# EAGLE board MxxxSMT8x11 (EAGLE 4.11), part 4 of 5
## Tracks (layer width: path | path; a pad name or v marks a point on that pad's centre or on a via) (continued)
M5  (via drill 0.61) (continued)
  Bottom 0.254: v88.9,160.02 v83.82,160.02 83.57,160.27 72.64,160.27 v72.39,160.53 | v100.33,162.81 99.31,163.83 92.71,163.83 v90.17,161.29 | v22.86,167.39 13.97,167.39 U$9.M2 | v22.86,164.08 v35.56,164.08 35.81,164.08 55.63,164.08 v55.88,163.83
M6  (via drill 0.61)
  Top 0.254: E62.13 99.31,159 101.35,159 101.35,164.34 92.96,172.72 91.44,172.72 v91.44,169.16 91.44,164.85 92.46,163.83 E59.6 | v29.46,166.12 29.46,164.08 30.23,164.08 E56.6 32,163.83 32.51,163.32 32.51,162.05 v35.56,159 | v14.73,166.37 13.97,167.13 U$9.M1 | v45.72,167.13 v45.72,175.01 44.7,175.01 E44.2 | v49.53,159 50.55,159 E47.13 | v62.23,175.26 63.25,175.26 E51.13 | E54.12 74.68,176.28 v73.66,176.28 73.91,176.02 73.91,171.7 v75.18,170.43
  Bottom 0.254: v14.73,166.37 29.21,166.37 v29.46,166.12 29.72,166.37 44.96,166.37 v45.72,167.13 | v35.56,159 v49.53,159 | v45.72,175.01 61.98,175.01 v62.23,175.26 62.48,175.51 63.25,176.28 v73.66,176.28 | v91.44,169.16 91.19,169.42 76.2,169.42 v75.18,170.43
M7  (via drill 0.61)
  Top 0.254: v172.72,166.37 173.74,166.37 E74.3 | E80.12 168.66,166.37 v167.64,166.37 167.39,166.12 v166.37,165.1 | v184.15,165.86 184.15,165.35 185.17,165.35 E71.4 186.94,165.1 188.98,163.07 188.98,160.53 194.56,160.53 195.33,161.29 195.33,162.31 197.87,162.31 E68.6 199.64,162.56 v200.66,162.56 | v156.21,163.58 157.23,163.58 E83.10 | v233.68,159 v233.68,162.31 232.66,162.31 E77.9 | v220.98,162.31 219.96,162.31 E66.9
  Bottom 0.254: v167.64,166.37 v172.72,166.37 172.97,166.12 183.9,166.12 v184.15,165.86 | v156.21,163.58 157.23,162.56 163.83,162.56 v166.37,165.1 | v233.68,159 242.57,159 U$12.M2 | v233.68,162.31 v220.98,162.31 220.73,162.31 200.91,162.31 v200.66,162.56
M8  (via drill 0.61)
  Top 0.254: E83.13 157.23,167.39 155.19,167.39 155.19,162.05 163.58,153.67 165.1,153.67 v165.1,157.23 165.1,161.54 164.08,162.56 E80.6 | v227.08,160.27 227.08,162.31 226.31,162.31 E77.6 224.54,162.56 224.03,163.07 224.03,164.34 v220.98,167.39 | v241.81,160.02 242.57,159.26 U$12.M1 | v210.82,159.26 v210.82,151.38 211.84,151.38 E65.2 | v207.01,167.39 205.99,167.39 E68.13 | v194.31,151.13 193.29,151.13 E72.13 | E75.12 181.86,150.11 v182.88,150.11 182.63,150.37 182.63,154.69 v181.36,155.96
  Bottom 0.254: v241.81,160.02 227.33,160.02 v227.08,160.27 226.82,160.02 211.58,160.02 v210.82,159.26 | v220.98,167.39 v207.01,167.39 | v210.82,151.38 194.56,151.38 v194.31,151.13 194.06,150.88 193.29,150.11 v182.88,150.11 | v165.1,157.23 165.35,156.97 180.34,156.97 v181.36,155.96
M9  (via drill 0.61)
  Top 0.254: v172.72,100.33 173.74,100.33 E95.3 | E101.12 168.66,100.33 v167.64,100.33 167.39,100.08 v166.37,99.06 | v184.15,99.82 184.15,99.31 185.17,99.31 E92.4 186.94,99.06 188.98,97.03 188.98,94.49 194.56,94.49 195.33,95.25 195.33,96.27 197.87,96.27 E89.6 199.64,96.52 v200.66,96.52 | v156.21,97.54 157.23,97.54 E104.10 | v233.68,92.96 v233.68,96.27 232.66,96.27 E98.9 | v220.98,96.27 219.96,96.27 E87.9
  Bottom 0.254: v167.64,100.33 v172.72,100.33 172.97,100.08 183.9,100.08 v184.15,99.82 | v156.21,97.54 157.23,96.52 163.83,96.52 v166.37,99.06 | v233.68,92.96 242.57,92.96 U$15.M2 | v233.68,96.27 v220.98,96.27 220.73,96.27 200.91,96.27 v200.66,96.52
M10  (via drill 0.61)
  Top 0.254: E104.13 157.23,101.35 155.19,101.35 155.19,96.01 163.58,87.63 165.1,87.63 v165.1,91.19 165.1,95.5 164.08,96.52 E101.6 | v227.08,94.23 227.08,96.27 226.31,96.27 E98.6 224.54,96.52 224.03,97.03 224.03,98.3 v220.98,101.35 | v241.81,93.98 242.57,93.22 U$15.M1 | v210.82,93.22 v210.82,85.34 211.84,85.34 E86.2 | v207.01,101.35 205.99,101.35 E89.13 | v194.31,85.09 193.29,85.09 E93.13 | E96.12 181.86,84.07 v182.88,84.07 182.63,84.33 182.63,88.65 v181.36,89.92
  Bottom 0.254: v241.81,93.98 227.33,93.98 v227.08,94.23 226.82,93.98 211.58,93.98 v210.82,93.22 | v220.98,101.35 v207.01,101.35 | v210.82,85.34 194.56,85.34 v194.31,85.09 194.06,84.84 193.29,84.07 v182.88,84.07 | v165.1,91.19 165.35,90.93 180.34,90.93 v181.36,89.92
M11  (via drill 0.61)
  Top 0.254: v172.72,34.29 173.74,34.29 E116.3 | E122.12 168.66,34.29 v167.64,34.29 167.39,34.04 v166.37,33.02 | v184.15,33.78 184.15,33.27 185.17,33.27 E113.4 186.94,33.02 188.98,30.99 188.98,28.45 194.56,28.45 195.33,29.21 195.33,30.23 197.87,30.23 E110.6 199.64,30.48 v200.66,30.48 | v156.21,31.5 157.23,31.5 E125.10 | v233.68,26.92 v233.68,30.23 232.66,30.23 E119.9 | v220.98,30.23 219.96,30.23 E108.9
  Bottom 0.254: v167.64,34.29 v172.72,34.29 172.97,34.04 183.9,34.04 v184.15,33.78 | v156.21,31.5 157.23,30.48 163.83,30.48 v166.37,33.02 | v233.68,26.92 242.57,26.92 U$18.M2 | v233.68,30.23 v220.98,30.23 220.73,30.23 200.91,30.23 v200.66,30.48
M12  (via drill 0.61)
  Top 0.254: E125.13 157.23,35.31 155.19,35.31 155.19,29.97 163.58,21.59 165.1,21.59 v165.1,25.15 165.1,29.46 164.08,30.48 E122.6 | v227.08,28.19 227.08,30.23 226.31,30.23 E119.6 224.54,30.48 224.03,30.99 224.03,32.26 v220.98,35.31 | v241.81,27.94 242.57,27.18 U$18.M1 | v210.82,27.18 v210.82,19.3 211.84,19.3 E107.2 | v207.01,35.31 205.99,35.31 E110.13 | v194.31,19.05 193.29,19.05 E114.13 | E117.12 181.86,18.03 v182.88,18.03 182.63,18.29 182.63,22.61 v181.36,23.88
  Bottom 0.254: v241.81,27.94 227.33,27.94 v227.08,28.19 226.82,27.94 211.58,27.94 v210.82,27.18 | v220.98,35.31 v207.01,35.31 | v210.82,19.3 194.56,19.3 v194.31,19.05 194.06,18.8 193.29,18.03 v182.88,18.03 | v165.1,25.15 165.35,24.89 180.34,24.89 v181.36,23.88
N1  (via drill 0.61)
  Top 0.254: 95,43.43 95,41.91 98.81,38.1 100.58,38.1 v100.58,39.12 | 95,43.43 95,44.2 94.23,44.2 E18.3 | v104.9,40.64 104.9,41.66 E21.1 | E6.3 44.7,44.7 44.7,44.96 46.99,44.96 47.75,44.2 v47.75,36.58 47.75,28.19 50.55,28.19 E8.12 52.32,27.94 54.36,29.97 54.36,31.75 56.39,33.78 56.39,37.85 55.88,38.35 55.88,40.64 57.4,40.64 58.42,39.62 58.42,38.1 65.02,38.1 66.04,39.12 v66.04,42.16 66.04,44.2 65.02,44.2 E12.12 | v29.46,40.89 30.23,41.66 E3.1 | 77.47,45.47 76.45,45.47 E15.11 | v77.47,42.16 77.47,45.47 | v95.25,43.43 95,43.43 | v77.72,49.02 77.47,48.77 77.47,45.47 | v14.99,39.62 13.97,39.62 U$1.N1
  Bottom 0.254: v100.58,39.12 102.11,40.64 v104.9,40.64 | v29.46,40.89 29.21,40.64 25.15,40.64 | 25.15,40.64 24.13,39.62 24.13,37.34 32.51,37.34 32.77,37.59 39.12,37.59 39.62,37.08 43.94,37.08 44.45,36.58 v47.75,36.58 | v66.04,42.16 v77.47,42.16 | v95.25,43.43 92.96,45.72 92.96,47.24 92.71,47.24 90.93,49.02 v77.72,49.02 | v14.99,39.62 19.05,39.62 20.07,40.64 25.15,40.64
N2  (via drill 0.61)
  Top 0.254: v83.82,29.46 82.8,29.46 E14.4 | v88.9,30.48 87.88,30.48 E17.10 | v72.39,30.48 71.37,30.48 E11.5 | v105.16,34.29 105.16,33.27 E20.7 | v80.01,55.37 78.74,54.1 78.74,40.13 77.98,39.37 v77.98,30.73 | E2.8 24.13,33.27 v24.13,35.31 23.88,35.56 21.34,38.1 21.34,52.58 v21.84,53.09 | v31.75,35.31 31.75,34.29 34.54,34.29 35.56,33.27 36.58,33.27 E5.8 38.35,33.02 v39.37,33.02 | v49.53,33.02 49.53,29.46 50.55,29.46 E8.11
  Bottom 0.254: 84.84,30.48 v83.82,29.46 | 84.84,30.48 v88.9,30.48 | 77.98,30.48 84.84,30.48 | 77.98,30.48 v72.39,30.48 | v105.16,34.29 107.19,36.32 107.7,36.32 108.71,37.34 108.71,58.42 83.06,58.42 v80.01,55.37 79.76,55.63 76.96,58.42 57.15,58.42 51.82,53.09 v21.84,53.09 | v77.98,30.73 77.98,30.48 | U$1.N2 13.97,38.1 21.34,38.1 v24.13,35.31 24.38,35.31 v31.75,35.31 | v49.53,33.02 49.02,32.51 39.88,32.51 v39.37,33.02
N3  (via drill 0.61)
  Top 0.254: v83.82,95.5 82.8,95.5 E32.4 | v88.9,96.52 87.88,96.52 E38.10 | v72.39,96.52 71.37,96.52 E29.5 | v105.16,100.33 105.16,99.31 E41.7 | v80.01,121.41 78.74,120.14 78.74,106.17 77.98,105.41 v77.98,96.77 | E35.8 24.13,99.31 v24.13,101.35 23.88,101.6 21.34,104.14 21.34,118.62 v21.84,119.13 | v31.75,101.35 31.75,100.33 34.54,100.33 35.56,99.31 36.58,99.31 E24.8 38.35,99.06 v39.37,99.06 | v49.53,99.06 49.53,95.5 50.55,95.5 E26.11
  Bottom 0.254: 84.84,96.52 v83.82,95.5 | 84.84,96.52 v88.9,96.52 | 77.98,96.52 84.84,96.52 | 77.98,96.52 v72.39,96.52 | v105.16,100.33 107.19,102.36 107.7,102.36 108.71,103.38 108.71,124.46 83.06,124.46 v80.01,121.41 79.76,121.67 76.96,124.46 57.15,124.46 51.82,119.13 v21.84,119.13 | v77.98,96.77 77.98,96.52 | U$6.N2 13.97,104.14 21.34,104.14 v24.13,101.35 24.38,101.35 v31.75,101.35 | v49.53,99.06 49.02,98.55 39.88,98.55 v39.37,99.06
N4  (via drill 0.61)
  Top 0.254: 95,109.47 95,107.95 98.81,104.14 100.58,104.14 v100.58,105.16 | 95,109.47 95,110.24 94.23,110.24 E39.3 | v104.9,106.68 104.9,107.7 E42.1 | E23.3 44.7,110.74 44.7,111 46.99,111 47.75,110.24 v47.75,102.62 47.75,94.23 50.55,94.23 E26.12 52.32,93.98 54.36,96.01 54.36,97.79 56.39,99.82 56.39,103.89 55.88,104.39 55.88,106.68 57.4,106.68 58.42,105.66 58.42,104.14 65.02,104.14 66.04,105.16 v66.04,108.2 66.04,110.24 65.02,110.24 E30.12 | v29.46,106.93 30.23,107.7 E36.1 | 77.47,111.51 76.45,111.51 E33.11 | v77.47,108.2 77.47,111.51 | v95.25,109.47 95,109.47 | v77.72,115.06 77.47,114.81 77.47,111.51 | v14.99,105.66 13.97,105.66 U$6.N1
  Bottom 0.254: v100.58,105.16 102.11,106.68 v104.9,106.68 | v29.46,106.93 29.21,106.68 25.15,106.68 | 25.15,106.68 24.13,105.66 24.13,103.38 32.51,103.38 32.77,103.63 39.12,103.63 39.62,103.12 43.94,103.12 44.45,102.62 v47.75,102.62 | v66.04,108.2 v77.47,108.2 | v95.25,109.47 92.96,111.76 92.96,113.28 92.71,113.28 90.93,115.06 v77.72,115.06 | v14.99,105.66 19.05,105.66 20.07,106.68 25.15,106.68
N5  (via drill 0.61)
  Top 0.254: v83.82,161.54 82.8,161.54 E53.4 | v88.9,162.56 87.88,162.56 E59.10 | v72.39,162.56 71.37,162.56 E50.5 | v105.16,166.37 105.16,165.35 E62.7 | v80.01,187.45 78.74,186.18 78.74,172.21 77.98,171.45 v77.98,162.81 | E56.8 24.13,165.35 v24.13,167.39 23.88,167.64 21.34,170.18 21.34,184.66 v21.84,185.17 | v31.75,167.39 31.75,166.37 34.54,166.37 35.56,165.35 36.58,165.35 E45.8 38.35,165.1 v39.37,165.1 | v49.53,165.1 49.53,161.54 50.55,161.54 E47.11
  Bottom 0.254: 84.84,162.56 v83.82,161.54 | 84.84,162.56 v88.9,162.56 | 77.98,162.56 84.84,162.56 | 77.98,162.56 v72.39,162.56 | v105.16,166.37 107.19,168.4 107.7,168.4 108.71,169.42 108.71,190.5 83.06,190.5 v80.01,187.45 79.76,187.71 76.96,190.5 57.15,190.5 51.82,185.17 v21.84,185.17 | v77.98,162.81 77.98,162.56 | U$9.N2 13.97,170.18 21.34,170.18 v24.13,167.39 24.38,167.39 v31.75,167.39 | v49.53,165.1 49.02,164.59 39.88,164.59 v39.37,165.1
N6  (via drill 0.61)
  Top 0.254: 95,175.51 95,173.99 98.81,170.18 100.58,170.18 v100.58,171.2 | 95,175.51 95,176.28 94.23,176.28 E60.3 | v104.9,172.72 104.9,173.74 E63.1 | E44.3 44.7,176.78 44.7,177.04 46.99,177.04 47.75,176.28 v47.75,168.66 47.75,160.27 50.55,160.27 E47.12 52.32,160.02 54.36,162.05 54.36,163.83 56.39,165.86 56.39,169.93 55.88,170.43 55.88,172.72 57.4,172.72 58.42,171.7 58.42,170.18 65.02,170.18 66.04,171.2 v66.04,174.24 66.04,176.28 65.02,176.28 E51.12 | v29.46,172.97 30.23,173.74 E57.1 | 77.47,177.55 76.45,177.55 E54.11 | 77.47,177.55 v77.47,174.24 | v95.25,175.51 95,175.51 | v77.72,181.1 77.47,180.85 77.47,177.55 | v14.99,171.7 13.97,171.7 U$9.N1
  Bottom 0.254: v100.58,171.2 102.11,172.72 v104.9,172.72 | v29.46,172.97 29.21,172.72 25.15,172.72 | 25.15,172.72 24.13,171.7 24.13,169.42 32.51,169.42 32.77,169.67 39.12,169.67 39.62,169.16 43.94,169.16 44.45,168.66 v47.75,168.66 | v77.47,174.24 v66.04,174.24 | v95.25,175.51 92.96,177.8 92.96,179.32 92.71,179.32 90.93,181.1 v77.72,181.1 | v14.99,171.7 19.05,171.7 20.07,172.72 25.15,172.72
N7  (via drill 0.61)
  Top 0.254: v172.72,164.85 173.74,164.85 E74.4 | v167.64,163.83 168.66,163.83 E80.10 | v184.15,163.83 185.17,163.83 E71.5 | v151.38,160.02 151.38,161.04 E83.7 | v176.53,138.94 177.8,140.21 177.8,154.18 178.56,154.94 v178.56,163.58 | E77.8 232.41,161.04 v232.41,159 232.66,158.75 235.2,156.21 235.2,141.73 v234.7,141.22 | v224.79,159 224.79,160.02 222,160.02 220.98,161.04 219.96,161.04 E66.8 218.19,161.29 v217.17,161.29 | v207.01,161.29 207.01,164.85 205.99,164.85 E68.11
  Bottom 0.254: 171.7,163.83 v172.72,164.85 | 171.7,163.83 v167.64,163.83 | 178.56,163.83 171.7,163.83 | 178.56,163.83 v184.15,163.83 | v151.38,160.02 149.35,157.99 148.84,157.99 147.83,156.97 147.83,135.89 173.48,135.89 v176.53,138.94 176.78,138.68 179.58,135.89 199.39,135.89 204.72,141.22 v234.7,141.22 | v178.56,163.58 178.56,163.83 | U$12.N2 242.57,156.21 235.2,156.21 v232.41,159 232.16,159 v224.79,159 | v207.01,161.29 207.52,161.8 216.66,161.8 v217.17,161.29
N8  (via drill 0.61)
  Top 0.254: 161.54,150.88 161.54,152.4 157.73,156.21 155.96,156.21 v155.96,155.19 | 161.54,150.88 161.54,150.11 162.31,150.11 E81.3 | v151.64,153.67 151.64,152.65 E84.1 | E65.3 211.84,149.61 211.84,149.35 209.55,149.35 208.79,150.11 v208.79,157.73 208.79,166.12 205.99,166.12 E68.12 204.22,166.37 202.18,164.34 202.18,162.56 200.15,160.53 200.15,156.46 200.66,155.96 200.66,153.67 199.14,153.67 198.12,154.69 198.12,156.21 191.52,156.21 190.5,155.19 v190.5,152.15 190.5,150.11 191.52,150.11 E72.12 | v227.08,153.42 226.31,152.65 E78.1 | 179.07,148.84 180.09,148.84 E75.11 | 179.07,148.84 v179.07,152.15 | 161.54,150.88 v161.29,150.88 | v178.82,145.29 179.07,145.54 179.07,148.84 | v241.55,154.69 242.57,154.69 U$12.N1
  Bottom 0.254: v155.96,155.19 154.43,153.67 v151.64,153.67 | v227.08,153.42 227.33,153.67 231.39,153.67 | 231.39,153.67 232.41,154.69 232.41,156.97 224.03,156.97 223.77,156.72 217.42,156.72 216.92,157.23 212.6,157.23 212.09,157.73 v208.79,157.73 | v179.07,152.15 v190.5,152.15 | v161.29,150.88 163.58,148.59 163.58,147.07 163.83,147.07 165.61,145.29 v178.82,145.29 | v241.55,154.69 237.49,154.69 236.47,153.67 231.39,153.67
N9  (via drill 0.61)
  Top 0.254: v172.72,98.81 173.74,98.81 E95.4 | v167.64,97.79 168.66,97.79 E101.10 | v184.15,97.79 185.17,97.79 E92.5 | v151.38,93.98 151.38,95 E104.7 | v176.53,72.9 177.8,74.17 177.8,88.14 178.56,88.9 v178.56,97.54 | E98.8 232.41,95 v232.41,92.96 232.66,92.71 235.2,90.17 235.2,75.69 v234.7,75.18 | v224.79,92.96 224.79,93.98 222,93.98 220.98,95 219.96,95 E87.8 218.19,95.25 v217.17,95.25 | v207.01,95.25 207.01,98.81 205.99,98.81 E89.11
  Bottom 0.254: 171.7,97.79 v172.72,98.81 | v167.64,97.79 171.7,97.79 | 171.7,97.79 178.56,97.79 | 178.56,97.79 v184.15,97.79 | v151.38,93.98 149.35,91.95 148.84,91.95 147.83,90.93 147.83,69.85 173.48,69.85 v176.53,72.9 176.78,72.64 179.58,69.85 199.39,69.85 204.72,75.18 v234.7,75.18 | 178.56,97.79 v178.56,97.54 | U$15.N2 242.57,90.17 235.2,90.17 v232.41,92.96 232.16,92.96 v224.79,92.96 | v207.01,95.25 207.52,95.76 216.66,95.76 v217.17,95.25
N10  (via drill 0.61)
  Top 0.254: 161.54,84.84 161.54,86.36 157.73,90.17 155.96,90.17 v155.96,89.15 | 161.54,84.84 161.54,84.07 162.31,84.07 E102.3 | v151.64,87.63 151.64,86.61 E105.1 | E86.3 211.84,83.57 211.84,83.31 209.55,83.31 208.79,84.07 v208.79,91.69 208.79,100.08 205.99,100.08 E89.12 204.22,100.33 202.18,98.3 202.18,96.52 200.15,94.49 200.15,90.42 200.66,89.92 200.66,87.63 199.14,87.63 198.12,88.65 198.12,90.17 191.52,90.17 190.5,89.15 v190.5,86.11 190.5,84.07 191.52,84.07 E93.12 | v227.08,87.38 226.31,86.61 E99.1 | 179.07,82.8 180.09,82.8 E96.11 | 179.07,82.8 v179.07,86.11 | v161.29,84.84 161.54,84.84 | v178.82,79.25 179.07,79.5 179.07,82.8 | v241.55,88.65 242.57,88.65 U$15.N1
  Bottom 0.254: v155.96,89.15 154.43,87.63 v151.64,87.63 | v227.08,87.38 227.33,87.63 231.39,87.63 | 231.39,87.63 232.41,88.65 232.41,90.93 224.03,90.93 223.77,90.68 217.42,90.68 216.92,91.19 212.6,91.19 212.09,91.69 v208.79,91.69 | v179.07,86.11 v190.5,86.11 | v161.29,84.84 163.58,82.55 163.58,81.03 163.83,81.03 165.61,79.25 v178.82,79.25 | v241.55,88.65 237.49,88.65 236.47,87.63 231.39,87.63
N11  (via drill 0.61)
  Top 0.254: v172.72,32.77 173.74,32.77 E116.4 | v167.64,31.75 168.66,31.75 E122.10 | v184.15,31.75 185.17,31.75 E113.5 | v151.38,27.94 151.38,28.96 E125.7 | v176.53,6.86 177.8,8.13 177.8,22.1 178.56,22.86 v178.56,31.5 | E119.8 232.41,28.96 v232.41,26.92 232.66,26.67 235.2,24.13 235.2,9.65 v234.7,9.14 | v224.79,26.92 224.79,27.94 222,27.94 220.98,28.96 219.96,28.96 E108.8 218.19,29.21 v217.17,29.21 | v207.01,29.21 207.01,32.77 205.99,32.77 E110.11
  Bottom 0.254: 171.7,31.75 v172.72,32.77 | 171.7,31.75 v167.64,31.75 | 178.56,31.75 171.7,31.75 | 178.56,31.75 v184.15,31.75 | v151.38,27.94 149.35,25.91 148.84,25.91 147.83,24.89 147.83,3.81 173.48,3.81 v176.53,6.86 176.78,6.6 179.58,3.81 199.39,3.81 204.72,9.14 v234.7,9.14 | v178.56,31.5 178.56,31.75 | U$18.N2 242.57,24.13 235.2,24.13 v232.41,26.92 232.16,26.92 v224.79,26.92 | v207.01,29.21 207.52,29.72 216.66,29.72 v217.17,29.21
N12  (via drill 0.61)
  Top 0.254: 161.54,18.8 161.54,20.32 157.73,24.13 155.96,24.13 v155.96,23.11 | 161.54,18.8 161.54,18.03 162.31,18.03 E123.3 | v151.64,21.59 151.64,20.57 E126.1 | E107.3 211.84,17.53 211.84,17.27 209.55,17.27 208.79,18.03 v208.79,25.65 208.79,34.04 205.99,34.04 E110.12 204.22,34.29 202.18,32.26 202.18,30.48 200.15,28.45 200.15,24.38 200.66,23.88 200.66,21.59 199.14,21.59 198.12,22.61 198.12,24.13 191.52,24.13 190.5,23.11 v190.5,20.07 190.5,18.03 191.52,18.03 E114.12 | v227.08,21.34 226.31,20.57 E120.1 | 179.07,16.76 180.09,16.76 E117.11 | v179.07,20.07 179.07,16.76 | v161.29,18.8 161.54,18.8 | v178.82,13.21 179.07,13.46 179.07,16.76 | v241.55,22.61 242.57,22.61 U$18.N1
  Bottom 0.254: v155.96,23.11 154.43,21.59 v151.64,21.59 | v227.08,21.34 227.33,21.59 231.39,21.59 | 231.39,21.59 232.41,22.61 232.41,24.89 224.03,24.89 223.77,24.64 217.42,24.64 216.92,25.15 212.6,25.15 212.09,25.65 v208.79,25.65 | v190.5,20.07 v179.07,20.07 | v161.29,18.8 163.58,16.51 163.58,14.99 163.83,14.99 165.61,13.21 v178.82,13.21 | v241.55,22.61 237.49,22.61 236.47,21.59 231.39,21.59
P1  (via drill 0.61)
  Top 0.254: v29.21,42.93 30.23,42.93 E3.2 32,42.93 33.02,42.93 v33.02,36.58 | v14.99,41.66 13.97,41.66 U$1.P1 | v47.24,46.48 47.24,45.72 44.7,45.72 E6.4 42.93,45.72 40.89,43.69 40.89,36.07 v40.39,35.56 | v54.86,46.74 54.86,43.94 56.9,41.91 E9.1 58.67,42.16 61.21,42.16 61.21,44.96 63.25,46.99 E12.10 65.02,47.24 65.79,47.24 v65.79,51.31 | v91.44,44.45 91.69,44.2 91.69,43.94 92.46,43.18 E18.2 | E15.5 81.03,46.99 v80.01,46.99 80.01,47.24 v80.01,50.8 | v106.17,50.55 106.17,44.7 105.66,44.7 E21.3
  Bottom 0.254: v29.21,42.93 27.94,41.66 v14.99,41.66 | v47.24,46.48 47.5,46.74 v54.86,46.74 | v80.01,46.99 80.52,46.48 89.41,46.48 v91.44,44.45 | v106.17,50.55 100.84,55.88 89.41,55.88 86.87,53.34 85.85,53.34 83.31,50.8 v80.01,50.8 79.76,51.05 79.25,51.56 66.04,51.56 v65.79,51.31 | v33.02,36.58 34.04,35.56 v40.39,35.56
P2  (via drill 0.61)
  Top 0.254: v53.34,30.73 52.32,30.73 E8.10 | v68.58,31.75 69.6,31.75 E11.6 71.37,31.75 71.88,32.26 71.88,32.77 74.68,32.77 E14.8 | E17.9 87.88,32 v88.9,32 89.15,32.26 89.15,33.27 v89.92,34.04 | v100.33,32 99.31,32 E20.9 | 39.88,42.93 38.35,42.93 E6.13 | 39.88,42.93 39.88,36.32 39.12,35.56 34.04,35.56 | 34.04,35.56 34.04,42.67 32,44.7 E3.3 | 34.04,35.56 33.02,35.56 v33.02,35.31 | v19.81,39.12 17.53,39.12 v17.53,40.64 | v46.74,43.94 v46.74,30.99 | 39.88,42.93 v39.88,43.94
  Bottom 0.254: v88.9,32 88.14,32.77 69.6,32.77 68.83,32 v68.58,31.75 67.56,30.73 v53.34,30.73 53.09,30.99 v46.74,30.99 | v100.33,32 98.3,34.04 v89.92,34.04 | v33.02,35.31 31.5,36.83 23.88,36.83 21.59,39.12 v19.81,39.12 | v17.53,40.64 14.73,40.64 13.97,41.4 U$1.P2 | v39.88,43.94 v46.74,43.94
P3  (via drill 0.61)
  Top 0.254: v53.34,96.77 52.32,96.77 E26.10 | v68.58,97.79 69.6,97.79 E29.6 71.37,97.79 71.88,98.3 71.88,98.81 74.68,98.81 E32.8 | E38.9 87.88,98.04 v88.9,98.04 89.15,98.3 89.15,99.31 v89.92,100.08 | v100.33,98.04 99.31,98.04 E41.9 | 39.88,108.97 38.35,108.97 E23.13 | 39.88,108.97 39.88,102.36 39.12,101.6 34.04,101.6 | 34.04,101.6 34.04,108.71 32,110.74 E36.3 | 34.04,101.6 33.02,101.6 v33.02,101.35 | v19.81,105.16 17.53,105.16 v17.53,106.68 | v46.74,109.98 v46.74,97.03 | 39.88,108.97 v39.88,109.98
  Bottom 0.254: v88.9,98.04 88.14,98.81 69.6,98.81 68.83,98.04 v68.58,97.79 67.56,96.77 v53.34,96.77 53.09,97.03 v46.74,97.03 | v100.33,98.04 98.3,100.08 v89.92,100.08 | v33.02,101.35 31.5,102.87 23.88,102.87 21.59,105.16 v19.81,105.16 | v17.53,106.68 14.73,106.68 13.97,107.44 U$6.P2 | v39.88,109.98 v46.74,109.98
P4  (via drill 0.61)
  Top 0.254: v29.21,108.97 30.23,108.97 E36.2 32,108.97 33.02,108.97 v33.02,102.62 | v14.99,107.7 13.97,107.7 U$6.P1 | v47.24,112.52 47.24,111.76 44.7,111.76 E23.4 42.93,111.76 40.89,109.73 40.89,102.11 v40.39,101.6 | v54.86,112.78 54.86,109.98 56.9,107.95 E27.1 58.67,108.2 61.21,108.2 61.21,111 63.25,113.03 E30.10 65.02,113.28 65.79,113.28 v65.79,117.35 | v91.44,110.49 91.69,110.24 91.69,109.98 92.46,109.22 E39.2 | E33.5 81.03,113.03 v80.01,113.03 80.01,113.28 v80.01,116.84 | v106.17,116.59 106.17,110.74 105.66,110.74 E42.3
  Bottom 0.254: v29.21,108.97 27.94,107.7 v14.99,107.7 | v47.24,112.52 47.5,112.78 v54.86,112.78 | v80.01,113.03 80.52,112.52 89.41,112.52 v91.44,110.49 | v106.17,116.59 100.84,121.92 89.41,121.92 86.87,119.38 85.85,119.38 83.31,116.84 v80.01,116.84 79.76,117.09 79.25,117.6 66.04,117.6 v65.79,117.35 | v33.02,102.62 34.04,101.6 v40.39,101.6
P5  (via drill 0.61)
  Top 0.254: v53.34,162.81 52.32,162.81 E47.10 | v68.58,163.83 69.6,163.83 E50.6 71.37,163.83 71.88,164.34 71.88,164.85 74.68,164.85 E53.8 | E59.9 87.88,164.08 v88.9,164.08 89.15,164.34 89.15,165.35 v89.92,166.12 | v100.33,164.08 99.31,164.08 E62.9 | 39.88,175.01 38.35,175.01 E44.13 | 39.88,175.01 39.88,168.4 39.12,167.64 34.04,167.64 | 34.04,167.64 34.04,174.75 32,176.78 E57.3 | 34.04,167.64 33.02,167.64 v33.02,167.39 | v19.81,171.2 17.53,171.2 v17.53,172.72 | v46.74,163.07 v46.74,176.02 | v39.88,176.02 39.88,175.01
  Bottom 0.254: v88.9,164.08 88.14,164.85 69.6,164.85 68.83,164.08 v68.58,163.83 67.56,162.81 v53.34,162.81 53.09,163.07 v46.74,163.07 | v100.33,164.08 98.3,166.12 v89.92,166.12 | v33.02,167.39 31.5,168.91 23.88,168.91 21.59,171.2 v19.81,171.2 | v17.53,172.72 14.73,172.72 13.97,173.48 U$9.P2 | v46.74,176.02 v39.88,176.02
P6  (via drill 0.61)
  Top 0.254: v29.21,175.01 30.23,175.01 E57.2 32,175.01 33.02,175.01 v33.02,168.66 | v14.99,173.74 13.97,173.74 U$9.P1 | v47.24,178.56 47.24,177.8 44.7,177.8 E44.4 42.93,177.8 40.89,175.77 40.89,168.15 v40.39,167.64 | v54.86,178.82 54.86,176.02 56.9,173.99 E48.1 58.67,174.24 61.21,174.24 61.21,177.04 63.25,179.07 E51.10 65.02,179.32 65.79,179.32 v65.79,183.39 | v91.44,176.53 91.69,176.28 91.69,176.02 92.46,175.26 E60.2 | E54.5 81.03,179.07 v80.01,179.07 80.01,179.32 v80.01,182.88 | v106.17,182.63 106.17,176.78 105.66,176.78 E63.3
  Bottom 0.254: v29.21,175.01 27.94,173.74 v14.99,173.74 | v47.24,178.56 47.5,178.82 v54.86,178.82 | v80.01,179.07 80.52,178.56 89.41,178.56 v91.44,176.53 | v106.17,182.63 100.84,187.96 89.41,187.96 86.87,185.42 85.85,185.42 83.31,182.88 v80.01,182.88 79.76,183.13 79.25,183.64 66.04,183.64 v65.79,183.39 | v33.02,168.66 34.04,167.64 v40.39,167.64
P7  (via drill 0.61)
  Top 0.254: v203.2,163.58 204.22,163.58 E68.10 | v187.96,162.56 186.94,162.56 E71.6 185.17,162.56 184.66,162.05 184.66,161.54 181.86,161.54 E74.8 | E80.9 168.66,162.31 v167.64,162.31 167.39,162.05 167.39,161.04 v166.62,160.27 | v156.21,162.31 157.23,162.31 E83.9 | 216.66,151.38 218.19,151.38 E65.13 | 216.66,151.38 216.66,157.99 217.42,158.75 222.5,158.75 | 222.5,158.75 222.5,151.64 224.54,149.61 E78.3 | 222.5,158.75 223.52,158.75 v223.52,159 | v236.73,155.19 239.01,155.19 v239.01,153.67 | v209.8,163.32 v209.8,150.37 | v216.66,150.37 216.66,151.38
  Bottom 0.254: v167.64,162.31 168.4,161.54 186.94,161.54 187.71,162.31 v187.96,162.56 188.98,163.58 v203.2,163.58 203.45,163.32 v209.8,163.32 | v156.21,162.31 158.24,160.27 v166.62,160.27 | v223.52,159 225.04,157.48 232.66,157.48 234.95,155.19 v236.73,155.19 | v239.01,153.67 241.81,153.67 242.57,152.91 U$12.P2 | v209.8,150.37 v216.66,150.37
P8  (via drill 0.61)
  Top 0.254: v227.33,151.38 226.31,151.38 E78.2 224.54,151.38 223.52,151.38 v223.52,157.73 | v241.55,152.65 242.57,152.65 U$12.P1 | v209.3,147.83 209.3,148.59 211.84,148.59 E65.4 213.61,148.59 215.65,150.62 215.65,158.24 v216.15,158.75 | v201.68,147.57 201.68,150.37 199.64,152.4 E69.1 197.87,152.15 195.33,152.15 195.33,149.35 193.29,147.32 E72.10 191.52,147.07 190.75,147.07 v190.75,143 | v165.1,149.86 164.85,150.11 164.85,150.37 164.08,151.13 E81.2 | E75.5 175.51,147.32 v176.53,147.32 176.53,147.07 v176.53,143.51 | v150.37,143.76 150.37,149.61 150.88,149.61 E84.3
  Bottom 0.254: v227.33,151.38 228.6,152.65 v241.55,152.65 | v209.3,147.83 209.04,147.57 v201.68,147.57 | v176.53,147.32 176.02,147.83 167.13,147.83 v165.1,149.86 | v150.37,143.76 155.7,138.43 167.13,138.43 169.67,140.97 170.69,140.97 173.23,143.51 v176.53,143.51 176.78,143.26 177.29,142.75 190.5,142.75 v190.75,143 | v223.52,157.73 222.5,158.75 v216.15,158.75
P9  (via drill 0.61)
  Top 0.254: v203.2,97.54 204.22,97.54 E89.10 | v187.96,96.52 186.94,96.52 E92.6 185.17,96.52 184.66,96.01 184.66,95.5 181.86,95.5 E95.8 | E101.9 168.66,96.27 v167.64,96.27 167.39,96.01 167.39,95 v166.62,94.23 | v156.21,96.27 157.23,96.27 E104.9 | 216.66,85.34 218.19,85.34 E86.13 | 216.66,85.34 216.66,91.95 217.42,92.71 222.5,92.71 | 222.5,92.71 222.5,85.6 224.54,83.57 E99.3 | 222.5,92.71 223.52,92.71 v223.52,92.96 | v236.73,89.15 239.01,89.15 v239.01,87.63 | v209.8,97.28 v209.8,84.33 | v216.66,84.33 216.66,85.34
  Bottom 0.254: v167.64,96.27 168.4,95.5 186.94,95.5 187.71,96.27 v187.96,96.52 188.98,97.54 v203.2,97.54 203.45,97.28 v209.8,97.28 | v156.21,96.27 158.24,94.23 v166.62,94.23 | v223.52,92.96 225.04,91.44 232.66,91.44 234.95,89.15 v236.73,89.15 | v239.01,87.63 241.81,87.63 242.57,86.87 U$15.P2 | v209.8,84.33 v216.66,84.33
P10  (via drill 0.61)
  Top 0.254: v227.33,85.34 226.31,85.34 E99.2 224.54,85.34 223.52,85.34 v223.52,91.69 | v241.55,86.61 242.57,86.61 U$15.P1 | v209.3,81.79 209.3,82.55 211.84,82.55 E86.4 213.61,82.55 215.65,84.58 215.65,92.2 v216.15,92.71 | v201.68,81.53 201.68,84.33 199.64,86.36 E90.1 197.87,86.11 195.33,86.11 195.33,83.31 193.29,81.28 E93.10 191.52,81.03 190.75,81.03 v190.75,76.96 | v165.1,83.82 164.85,84.07 164.85,84.33 164.08,85.09 E102.2 | E96.5 175.51,81.28 v176.53,81.28 176.53,81.03 v176.53,77.47 | v150.37,77.72 150.37,83.57 150.88,83.57 E105.3
  Bottom 0.254: v227.33,85.34 228.6,86.61 v241.55,86.61 | v209.3,81.79 209.04,81.53 v201.68,81.53 | v176.53,81.28 176.02,81.79 167.13,81.79 v165.1,83.82 | v150.37,77.72 155.7,72.39 167.13,72.39 169.67,74.93 170.69,74.93 173.23,77.47 v176.53,77.47 176.78,77.22 177.29,76.71 190.5,76.71 v190.75,76.96 | v223.52,91.69 222.5,92.71 v216.15,92.71
P11  (via drill 0.61)
  Top 0.254: v203.2,31.5 204.22,31.5 E110.10 | v187.96,30.48 186.94,30.48 E113.6 185.17,30.48 184.66,29.97 184.66,29.46 181.86,29.46 E116.8 | E122.9 168.66,30.23 v167.64,30.23 167.39,29.97 167.39,28.96 v166.62,28.19 | v156.21,30.23 157.23,30.23 E125.9 | 216.66,19.3 218.19,19.3 E107.13 | 216.66,19.3 216.66,25.91 217.42,26.67 222.5,26.67 | 222.5,26.67 222.5,19.56 224.54,17.53 E120.3 | 222.5,26.67 223.52,26.67 v223.52,26.92 | v236.73,23.11 239.01,23.11 v239.01,21.59 | v209.8,18.29 v209.8,31.24 | 216.66,19.3 v216.66,18.29
  Bottom 0.254: v167.64,30.23 168.4,29.46 186.94,29.46 187.71,30.23 v187.96,30.48 188.98,31.5 v203.2,31.5 203.45,31.24 v209.8,31.24 | v156.21,30.23 158.24,28.19 v166.62,28.19 | v223.52,26.92 225.04,25.4 232.66,25.4 234.95,23.11 v236.73,23.11 | v239.01,21.59 241.81,21.59 242.57,20.83 U$18.P2 | v216.66,18.29 v209.8,18.29
P12  (via drill 0.61)
  Top 0.254: v227.33,19.3 226.31,19.3 E120.2 224.54,19.3 223.52,19.3 v223.52,25.65 | v241.55,20.57 242.57,20.57 U$18.P1 | v209.3,15.75 209.3,16.51 211.84,16.51 E107.4 213.61,16.51 215.65,18.54 215.65,26.16 v216.15,26.67 | v201.68,15.49 201.68,18.29 199.64,20.32 E111.1 197.87,20.07 195.33,20.07 195.33,17.27 193.29,15.24 E114.10 191.52,14.99 190.75,14.99 v190.75,10.92 | v165.1,17.78 164.85,18.03 164.85,18.29 164.08,19.05 E123.2 | E117.5 175.51,15.24 v176.53,15.24 176.53,14.99 v176.53,11.43 | v150.37,11.68 150.37,17.53 150.88,17.53 E126.3
  Bottom 0.254: v227.33,19.3 228.6,20.57 v241.55,20.57 | v209.3,15.75 209.04,15.49 v201.68,15.49 | v176.53,15.24 176.02,15.75 167.13,15.75 v165.1,17.78 | v150.37,11.68 155.7,6.35 167.13,6.35 169.67,8.89 170.69,8.89 173.23,11.43 v176.53,11.43 176.78,11.18 177.29,10.67 190.5,10.67 v190.75,10.92 | v223.52,25.65 222.5,26.67 v216.15,26.67
R1  (via drill 0.61)
  Top 0.254: v29.21,44.45 29.21,46.74 30.23,46.74 E3.5 32,46.99 34.04,46.99 v34.04,50.29 | v14.99,43.43 13.97,44.45 U$1.R1 | E21.14 97.54,42.16 96.27,42.16 96.27,43.69 94.23,45.72 E18.4 92.46,45.97 v91.44,45.97 | v55.88,44.2 56.9,43.18 E9.2 58.67,43.43 59.69,43.43 60.71,44.45 60.71,48.01 v62.23,48.01 63.25,48.01 E12.9 | E6.5 44.7,46.74 v45.72,46.74 45.47,46.99 45.47,50.29 v45.21,50.55 | v83.82,48.01 82.8,48.01 E15.6
  Bottom 0.254: v29.21,44.45 27.18,42.42 18.8,42.42 18.54,42.16 16.26,42.16 v14.99,43.43 | v45.72,46.74 48.26,44.2 v55.88,44.2 | v62.23,48.01 v83.82,48.01 84.07,47.75 89.66,47.75 v91.44,45.97 | v34.04,50.29 34.29,50.55 v45.21,50.55
R2  (via drill 0.61)
  Top 0.254: E3.4 32,45.47 34.54,45.47 35.31,44.7 36.58,44.7 E6.12 36.58,44.2 36.07,44.2 36.07,41.91 | v70.87,35.81 71.12,36.07 71.12,41.66 E12.1 | E8.9 52.32,32 53.34,32 v53.34,33.02 53.09,33.27 53.09,33.53 v51.56,35.05 | v78.99,35.81 78.99,39.62 81.03,41.66 E15.1 | v88.65,34.04 87.88,33.27 E17.8 | v96.52,33.02 97.54,33.02 E20.8 | 36.07,41.91 36.07,39.37 v38.86,36.58 | v16.51,43.18 18.8,40.89 v18.8,40.64 | v35.56,41.91 36.07,41.91
  Bottom 0.254: v53.34,33.02 53.59,32.77 56.13,32.77 57.66,31.24 66.29,31.24 v70.87,35.81 71.12,35.81 v78.99,35.81 79.25,35.56 80.77,34.04 v88.65,34.04 88.9,33.78 89.66,33.02 v96.52,33.02 | v38.86,36.58 43.69,36.58 44.2,36.07 46.99,36.07 48.01,35.05 v51.56,35.05 | v16.51,43.18 15.24,44.45 13.97,44.45 U$1.R2 | v18.8,40.64 19.3,41.15 28.45,41.15 29.21,41.91 v35.56,41.91
R3  (via drill 0.61)
  Top 0.254: E36.4 32,111.51 34.54,111.51 35.31,110.74 36.58,110.74 E23.12 36.58,110.24 36.07,110.24 36.07,107.95 | v70.87,101.85 71.12,102.11 71.12,107.7 E30.1 | E26.9 52.32,98.04 53.34,98.04 v53.34,99.06 53.09,99.31 53.09,99.57 v51.56,101.09 | v78.99,101.85 78.99,105.66 81.03,107.7 E33.1 | v88.65,100.08 87.88,99.31 E38.8 | v96.52,99.06 97.54,99.06 E41.8 | 36.07,107.95 36.07,105.41 v38.86,102.62 | v16.51,109.22 18.8,106.93 v18.8,106.68 | v35.56,107.95 36.07,107.95
  Bottom 0.254: v53.34,99.06 53.59,98.81 56.13,98.81 57.66,97.28 66.29,97.28 v70.87,101.85 71.12,101.85 v78.99,101.85 79.25,101.6 80.77,100.08 v88.65,100.08 88.9,99.82 89.66,99.06 v96.52,99.06 | v38.86,102.62 43.69,102.62 44.2,102.11 46.99,102.11 48.01,101.09 v51.56,101.09 | v16.51,109.22 15.24,110.49 13.97,110.49 U$6.R2 | v18.8,106.68 19.3,107.19 28.45,107.19 29.21,107.95 v35.56,107.95
R4  (via drill 0.61)
  Top 0.254: v29.21,110.49 29.21,112.78 30.23,112.78 E36.5 32,113.03 34.04,113.03 v34.04,116.33 | v14.99,109.47 13.97,110.49 U$6.R1 | E42.14 97.54,108.2 96.27,108.2 96.27,109.73 94.23,111.76 E39.4 92.46,112.01 v91.44,112.01 | v55.88,110.24 56.9,109.22 E27.2 58.67,109.47 59.69,109.47 60.71,110.49 60.71,114.05 v62.23,114.05 63.25,114.05 E30.9 | E23.5 44.7,112.78 v45.72,112.78 45.47,113.03 45.47,116.33 v45.21,116.59 | v83.82,114.05 82.8,114.05 E33.6
  Bottom 0.254: v29.21,110.49 27.18,108.46 18.8,108.46 18.54,108.2 16.26,108.2 v14.99,109.47 | v45.72,112.78 48.26,110.24 v55.88,110.24 | v62.23,114.05 v83.82,114.05 84.07,113.79 89.66,113.79 v91.44,112.01 | v34.04,116.33 34.29,116.59 v45.21,116.59
R5  (via drill 0.61)
  Top 0.254: E57.4 32,177.55 34.54,177.55 35.31,176.78 36.58,176.78 E44.12 36.58,176.28 36.07,176.28 36.07,173.99 | v70.87,167.89 71.12,168.15 71.12,173.74 E51.1 | E47.9 52.32,164.08 53.34,164.08 v53.34,165.1 53.09,165.35 53.09,165.61 v51.56,167.13 | v78.99,167.89 78.99,171.7 81.03,173.74 E54.1 | v88.65,166.12 87.88,165.35 E59.8 | v96.52,165.1 97.54,165.1 E62.8 | 36.07,173.99 36.07,171.45 v38.86,168.66 | v16.51,175.26 18.8,172.97 v18.8,172.72 | 36.07,173.99 v35.56,173.99
  Bottom 0.254: v53.34,165.1 53.59,164.85 56.13,164.85 57.66,163.32 66.29,163.32 v70.87,167.89 71.12,167.89 v78.99,167.89 79.25,167.64 80.77,166.12 v88.65,166.12 88.9,165.86 89.66,165.1 v96.52,165.1 | v38.86,168.66 43.69,168.66 44.2,168.15 46.99,168.15 48.01,167.13 v51.56,167.13 | v16.51,175.26 15.24,176.53 13.97,176.53 U$9.R2 | v18.8,172.72 19.3,173.23 28.45,173.23 29.21,173.99 v35.56,173.99
R6  (via drill 0.61)
  Top 0.254: v29.21,176.53 29.21,178.82 30.23,178.82 E57.5 32,179.07 34.04,179.07 v34.04,182.37 | v14.99,175.51 13.97,176.53 U$9.R1 | E63.14 97.54,174.24 96.27,174.24 96.27,175.77 94.23,177.8 E60.4 92.46,178.05 v91.44,178.05 | v55.88,176.28 56.9,175.26 E48.2 58.67,175.51 59.69,175.51 60.71,176.53 60.71,180.09 v62.23,180.09 63.25,180.09 E51.9 | E44.5 44.7,178.82 v45.72,178.82 45.47,179.07 45.47,182.37 v45.21,182.63 | v83.82,180.09 82.8,180.09 E54.6
  Bottom 0.254: v29.21,176.53 27.18,174.5 18.8,174.5 18.54,174.24 16.26,174.24 v14.99,175.51 | v45.72,178.82 48.26,176.28 v55.88,176.28 | v62.23,180.09 v83.82,180.09 84.07,179.83 89.66,179.83 v91.44,178.05 | v34.04,182.37 34.29,182.63 v45.21,182.63
R7  (via drill 0.61)
  Top 0.254: E78.4 224.54,148.84 222,148.84 221.23,149.61 219.96,149.61 E65.12 219.96,150.11 220.47,150.11 220.47,152.4 | v185.67,158.5 185.42,158.24 185.42,152.65 E72.1 | E68.9 204.22,162.31 203.2,162.31 v203.2,161.29 203.45,161.04 203.45,160.78 v204.98,159.26 | v177.55,158.5 177.55,154.69 175.51,152.65 E75.1 | v167.89,160.27 168.66,161.04 E80.8 | v160.02,161.29 159,161.29 E83.8 | 220.47,152.4 220.47,154.94 v217.68,157.73 | v240.03,151.13 237.74,153.42 v237.74,153.67 | 220.47,152.4 v220.98,152.4
  Bottom 0.254: v203.2,161.29 202.95,161.54 200.41,161.54 198.88,163.07 190.25,163.07 v185.67,158.5 185.42,158.5 v177.55,158.5 177.29,158.75 175.77,160.27 v167.89,160.27 167.64,160.53 166.88,161.29 v160.02,161.29 | v217.68,157.73 212.85,157.73 212.34,158.24 209.55,158.24 208.53,159.26 v204.98,159.26 | v240.03,151.13 241.3,149.86 242.57,149.86 U$12.R2 | v237.74,153.67 237.24,153.16 228.09,153.16 227.33,152.4 v220.98,152.4
R8  (via drill 0.61)
  Top 0.254: v227.33,149.86 227.33,147.57 226.31,147.57 E78.5 224.54,147.32 222.5,147.32 v222.5,144.02 | v241.55,150.88 242.57,149.86 U$12.R1 | E84.14 159,152.15 160.27,152.15 160.27,150.62 162.31,148.59 E81.4 164.08,148.34 v165.1,148.34 | v200.66,150.11 199.64,151.13 E69.2 197.87,150.88 196.85,150.88 195.83,149.86 195.83,146.3 v194.31,146.3 193.29,146.3 E72.9 | E65.5 211.84,147.57 v210.82,147.57 211.07,147.32 211.07,144.02 v211.33,143.76 | v172.72,146.3 173.74,146.3 E75.6
  Bottom 0.254: v227.33,149.86 229.36,151.89 237.74,151.89 238,152.15 240.28,152.15 v241.55,150.88 | v210.82,147.57 208.28,150.11 v200.66,150.11 | v194.31,146.3 v172.72,146.3 172.47,146.56 166.88,146.56 v165.1,148.34 | v222.5,144.02 222.25,143.76 v211.33,143.76
R9  (via drill 0.61)
  Top 0.254: E99.4 224.54,82.8 222,82.8 221.23,83.57 219.96,83.57 E86.12 219.96,84.07 220.47,84.07 220.47,86.36 | v185.67,92.46 185.42,92.2 185.42,86.61 E93.1 | E89.9 204.22,96.27 203.2,96.27 v203.2,95.25 203.45,95 203.45,94.74 v204.98,93.22 | v177.55,92.46 177.55,88.65 175.51,86.61 E96.1 | v167.89,94.23 168.66,95 E101.8 | v160.02,95.25 159,95.25 E104.8 | 220.47,86.36 220.47,88.9 v217.68,91.69 | v240.03,85.09 237.74,87.38 v237.74,87.63 | 220.47,86.36 v220.98,86.36
  Bottom 0.254: v203.2,95.25 202.95,95.5 200.41,95.5 198.88,97.03 190.25,97.03 v185.67,92.46 185.42,92.46 v177.55,92.46 177.29,92.71 175.77,94.23 v167.89,94.23 167.64,94.49 166.88,95.25 v160.02,95.25 | v217.68,91.69 212.85,91.69 212.34,92.2 209.55,92.2 208.53,93.22 v204.98,93.22 | v240.03,85.09 241.3,83.82 242.57,83.82 U$15.R2 | v237.74,87.63 237.24,87.12 228.09,87.12 227.33,86.36 v220.98,86.36
R10  (via drill 0.61)
  Top 0.254: v227.33,83.82 227.33,81.53 226.31,81.53 E99.5 224.54,81.28 222.5,81.28 v222.5,77.98 | v241.55,84.84 242.57,83.82 U$15.R1 | E105.14 159,86.11 160.27,86.11 160.27,84.58 162.31,82.55 E102.4 164.08,82.3 v165.1,82.3 | v200.66,84.07 199.64,85.09 E90.2 197.87,84.84 196.85,84.84 195.83,83.82 195.83,80.26 v194.31,80.26 193.29,80.26 E93.9 | E86.5 211.84,81.53 v210.82,81.53 211.07,81.28 211.07,77.98 v211.33,77.72 | v172.72,80.26 173.74,80.26 E96.6
  Bottom 0.254: v227.33,83.82 229.36,85.85 237.74,85.85 238,86.11 240.28,86.11 v241.55,84.84 | v210.82,81.53 208.28,84.07 v200.66,84.07 | v194.31,80.26 v172.72,80.26 172.47,80.52 166.88,80.52 v165.1,82.3 | v222.5,77.98 222.25,77.72 v211.33,77.72
R11  (via drill 0.61)
  Top 0.254: E120.4 224.54,16.76 222,16.76 221.23,17.53 219.96,17.53 E107.12 219.96,18.03 220.47,18.03 220.47,20.32 | v185.67,26.42 185.42,26.16 185.42,20.57 E114.1 | E110.9 204.22,30.23 203.2,30.23 v203.2,29.21 203.45,28.96 203.45,28.7 v204.98,27.18 | v177.55,26.42 177.55,22.61 175.51,20.57 E117.1 | v167.89,28.19 168.66,28.96 E122.8 | v160.02,29.21 159,29.21 E125.8 | 220.47,20.32 220.47,22.86 v217.68,25.65 | v240.03,19.05 237.74,21.34 v237.74,21.59 | v220.98,20.32 220.47,20.32
  Bottom 0.254: v203.2,29.21 202.95,29.46 200.41,29.46 198.88,30.99 190.25,30.99 v185.67,26.42 185.42,26.42 v177.55,26.42 177.29,26.67 175.77,28.19 v167.89,28.19 167.64,28.45 166.88,29.21 v160.02,29.21 | v217.68,25.65 212.85,25.65 212.34,26.16 209.55,26.16 208.53,27.18 v204.98,27.18 | v240.03,19.05 241.3,17.78 242.57,17.78 U$18.R2 | v237.74,21.59 237.24,21.08 228.09,21.08 227.33,20.32 v220.98,20.32
R12  (via drill 0.61)
  Top 0.254: v227.33,17.78 227.33,15.49 226.31,15.49 E120.5 224.54,15.24 222.5,15.24 v222.5,11.94 | v241.55,18.8 242.57,17.78 U$18.R1 | E126.14 159,20.07 160.27,20.07 160.27,18.54 162.31,16.51 E123.4 164.08,16.26 v165.1,16.26 | v200.66,18.03 199.64,19.05 E111.2 197.87,18.8 196.85,18.8 195.83,17.78 195.83,14.22 v194.31,14.22 193.29,14.22 E114.9 | E107.5 211.84,15.49 v210.82,15.49 211.07,15.24 211.07,11.94 v211.33,11.68 | v172.72,14.22 173.74,14.22 E117.6
  Bottom 0.254: v227.33,17.78 229.36,19.81 237.74,19.81 238,20.07 240.28,20.07 v241.55,18.8 | v210.82,15.49 208.28,18.03 v200.66,18.03 | v194.31,14.22 v172.72,14.22 172.47,14.48 166.88,14.48 v165.1,16.26 | v222.5,11.94 222.25,11.68 v211.33,11.68
S1  (via drill 0.61)
  Top 0.254: E21.12 97.54,44.7 96.01,44.7 96.01,44.96 95.5,45.47 95.5,45.72 94.23,46.99 E18.5 92.46,47.24 v91.44,47.24 | v33.02,48.01 32,48.01 E3.6 | v41.91,48.01 42.93,48.01 E6.6 | 53.85,43.43 52.32,43.43 E9.13 | 53.85,43.43 53.85,47.75 v54.1,48.01 | v62.23,49.28 63.25,49.28 E12.8 | v90.68,42.67 88.9,40.89 88.9,38.86 v86.36,36.32 | v55.37,37.59 53.85,39.12 53.85,43.43 | v14.99,49.02 13.97,49.02 U$1.S1
  Bottom 0.254: v62.23,49.28 61.21,48.26 54.36,48.26 v54.1,48.01 42.16,48.01 v41.91,48.01 v33.02,48.01 32.77,48.26 32,49.02 v14.99,49.02 | v91.44,47.24 92.46,46.23 92.46,42.67 v90.68,42.67 | v86.36,36.32 85.85,36.83 56.13,36.83 v55.37,37.59
S2  (via drill 0.61)
  Top 0.254: v80.01,43.18 81.03,43.18 E15.2 | E12.2 71.37,43.18 v72.39,43.18 72.64,43.43 72.64,49.28 73.66,50.29 v73.66,60.71 73.66,60.96 88.39,60.96 95.76,53.59 95.76,53.34 97.03,53.34 100.08,50.29 100.08,49.02 v100.84,48.26 | v85.09,45.47 86.11,45.47 E18.11 | v102.87,47.24 103.89,47.24 E21.5 | v22.86,43.43 23.88,43.43 E3.13 | v35.56,45.72 36.58,45.72 E6.11 38.35,45.72 39.12,46.48 39.12,57.66 v38.61,58.17 | v48.77,41.15 48.77,35.05 50.55,33.27 E8.8
  Bottom 0.254: v72.39,43.18 v80.01,43.18 80.26,43.43 83.06,43.43 v85.09,45.47 | v102.87,47.24 101.85,48.26 v100.84,48.26 | U$1.S2 13.97,47.75 18.54,47.75 v22.86,43.43 23.11,43.69 24.89,45.47 35.31,45.47 v35.56,45.72 35.81,45.47 39.88,41.4 48.51,41.4 v48.77,41.15 | v73.66,60.71 73.41,60.45 40.89,60.45 v38.61,58.17
S3  (via drill 0.61)
  Top 0.254: v80.01,109.22 81.03,109.22 E33.2 | E30.2 71.37,109.22 v72.39,109.22 72.64,109.47 72.64,115.32 73.66,116.33 v73.66,126.75 73.66,127 88.39,127 95.76,119.63 95.76,119.38 97.03,119.38 100.08,116.33 100.08,115.06 v100.84,114.3 | v85.09,111.51 86.11,111.51 E39.11 | v102.87,113.28 103.89,113.28 E42.5 | v22.86,109.47 23.88,109.47 E36.13 | v35.56,111.76 36.58,111.76 E23.11 38.35,111.76 39.12,112.52 39.12,123.7 v38.61,124.21 | v48.77,107.19 48.77,101.09 50.55,99.31 E26.8
  Bottom 0.254: v72.39,109.22 v80.01,109.22 80.26,109.47 83.06,109.47 v85.09,111.51 | v102.87,113.28 101.85,114.3 v100.84,114.3 | U$6.S2 13.97,113.79 18.54,113.79 v22.86,109.47 23.11,109.73 24.89,111.51 35.31,111.51 v35.56,111.76 35.81,111.51 39.88,107.44 48.51,107.44 v48.77,107.19 | v73.66,126.75 73.41,126.49 40.89,126.49 v38.61,124.21
S4  (via drill 0.61)
  Top 0.254: E42.12 97.54,110.74 96.01,110.74 96.01,111 95.5,111.51 95.5,111.76 94.23,113.03 E39.5 92.46,113.28 v91.44,113.28 | v33.02,114.05 32,114.05 E36.6 | v41.91,114.05 42.93,114.05 E23.6 | 53.85,109.47 52.32,109.47 E27.13 | 53.85,109.47 53.85,113.79 v54.1,114.05 | v62.23,115.32 63.25,115.32 E30.8 | v90.68,108.71 88.9,106.93 88.9,104.9 v86.36,102.36 | v55.37,103.63 53.85,105.16 53.85,109.47 | v14.99,115.06 13.97,115.06 U$6.S1
  Bottom 0.254: v62.23,115.32 61.21,114.3 54.36,114.3 v54.1,114.05 42.16,114.05 v41.91,114.05 v33.02,114.05 32.77,114.3 32,115.06 v14.99,115.06 | v91.44,113.28 92.46,112.27 92.46,108.71 v90.68,108.71 | v86.36,102.36 85.85,102.87 56.13,102.87 v55.37,103.63
S5  (via drill 0.61)
  Top 0.254: v80.01,175.26 81.03,175.26 E54.2 | E51.2 71.37,175.26 v72.39,175.26 72.64,175.51 72.64,181.36 73.66,182.37 v73.66,192.79 73.66,193.04 88.39,193.04 95.76,185.67 95.76,185.42 97.03,185.42 100.08,182.37 100.08,181.1 v100.84,180.34 | v85.09,177.55 86.11,177.55 E60.11 | v102.87,179.32 103.89,179.32 E63.5 | v22.86,175.51 23.88,175.51 E57.13 | v35.56,177.8 36.58,177.8 E44.11 38.35,177.8 39.12,178.56 39.12,189.74 v38.61,190.25 | v48.77,173.23 48.77,167.13 50.55,165.35 E47.8
  Bottom 0.254: v72.39,175.26 v80.01,175.26 80.26,175.51 83.06,175.51 v85.09,177.55 | v102.87,179.32 101.85,180.34 v100.84,180.34 | U$9.S2 13.97,179.83 18.54,179.83 v22.86,175.51 23.11,175.77 24.89,177.55 35.31,177.55 v35.56,177.8 35.81,177.55 39.88,173.48 48.51,173.48 v48.77,173.23 | v73.66,192.79 73.41,192.53 40.89,192.53 v38.61,190.25
S6  (via drill 0.61)
  Top 0.254: E63.12 97.54,176.78 96.01,176.78 96.01,177.04 95.5,177.55 95.5,177.8 94.23,179.07 E60.5 92.46,179.32 v91.44,179.32 | v33.02,180.09 32,180.09 E57.6 | v41.91,180.09 42.93,180.09 E44.6 | 53.85,175.51 52.32,175.51 E48.13 | 53.85,175.51 53.85,179.83 v54.1,180.09 | v62.23,181.36 63.25,181.36 E51.8 | v90.68,174.75 88.9,172.97 88.9,170.94 v86.36,168.4 | v55.37,169.67 53.85,171.2 53.85,175.51 | v14.99,181.1 13.97,181.1 U$9.S1
  Bottom 0.254: v62.23,181.36 61.21,180.34 54.36,180.34 v54.1,180.09 42.16,180.09 v41.91,180.09 v33.02,180.09 32.77,180.34 32,181.1 v14.99,181.1 | v91.44,179.32 92.46,178.31 92.46,174.75 v90.68,174.75 | v86.36,168.4 85.85,168.91 56.13,168.91 v55.37,169.67
S7  (via drill 0.61)
  Top 0.254: v176.53,151.13 175.51,151.13 E75.2 | E72.2 185.17,151.13 v184.15,151.13 183.9,150.88 183.9,145.03 182.88,144.02 v182.88,133.6 182.88,133.35 168.15,133.35 160.78,140.72 160.78,140.97 159.51,140.97 156.46,144.02 156.46,145.29 v155.7,146.05 | v171.45,148.84 170.43,148.84 E81.11 | v153.67,147.07 152.65,147.07 E84.5 | v233.68,150.88 232.66,150.88 E78.13 | v220.98,148.59 219.96,148.59 E65.11 218.19,148.59 217.42,147.83 217.42,136.65 v217.93,136.14 | v207.77,153.16 207.77,159.26 205.99,161.04 E68.8
  Bottom 0.254: v184.15,151.13 v176.53,151.13 176.28,150.88 173.48,150.88 v171.45,148.84 | v153.67,147.07 154.69,146.05 v155.7,146.05 | U$12.S2 242.57,146.56 238,146.56 v233.68,150.88 233.43,150.62 231.65,148.84 221.23,148.84 v220.98,148.59 220.73,148.84 216.66,152.91 208.03,152.91 v207.77,153.16 | v182.88,133.6 183.13,133.86 215.65,133.86 v217.93,136.14
S8  (via drill 0.61)
  Top 0.254: E84.12 159,149.61 160.53,149.61 160.53,149.35 161.04,148.84 161.04,148.59 162.31,147.32 E81.5 164.08,147.07 v165.1,147.07 | v223.52,146.3 224.54,146.3 E78.6 | v214.63,146.3 213.61,146.3 E65.6 | 202.69,150.88 204.22,150.88 E69.13 | 202.69,150.88 202.69,146.56 v202.44,146.3 | v194.31,145.03 193.29,145.03 E72.8 | v165.86,151.64 167.64,153.42 167.64,155.45 v170.18,157.99 | v201.17,156.72 202.69,155.19 202.69,150.88 | v241.55,145.29 242.57,145.29 U$12.S1
  Bottom 0.254: v194.31,145.03 195.33,146.05 202.18,146.05 v202.44,146.3 214.38,146.3 v214.63,146.3 v223.52,146.3 223.77,146.05 224.54,145.29 v241.55,145.29 | v165.1,147.07 164.08,148.08 164.08,151.64 v165.86,151.64 | v170.18,157.99 170.69,157.48 200.41,157.48 v201.17,156.72
S9  (via drill 0.61)
  Top 0.254: v176.53,85.09 175.51,85.09 E96.2 | E93.2 185.17,85.09 v184.15,85.09 183.9,84.84 183.9,78.99 182.88,77.98 v182.88,67.56 182.88,67.31 168.15,67.31 160.78,74.68 160.78,74.93 159.51,74.93 156.46,77.98 156.46,79.25 v155.7,80.01 | v171.45,82.8 170.43,82.8 E102.11 | v153.67,81.03 152.65,81.03 E105.5 | v233.68,84.84 232.66,84.84 E99.13 | v220.98,82.55 219.96,82.55 E86.11 218.19,82.55 217.42,81.79 217.42,70.61 v217.93,70.1 | v207.77,87.12 207.77,93.22 205.99,95 E89.8
  Bottom 0.254: v184.15,85.09 v176.53,85.09 176.28,84.84 173.48,84.84 v171.45,82.8 | v153.67,81.03 154.69,80.01 v155.7,80.01 | U$15.S2 242.57,80.52 238,80.52 v233.68,84.84 233.43,84.58 231.65,82.8 221.23,82.8 v220.98,82.55 220.73,82.8 216.66,86.87 208.03,86.87 v207.77,87.12 | v182.88,67.56 183.13,67.82 215.65,67.82 v217.93,70.1
S10  (via drill 0.61)
  Top 0.254: E105.12 159,83.57 160.53,83.57 160.53,83.31 161.04,82.8 161.04,82.55 162.31,81.28 E102.5 164.08,81.03 v165.1,81.03 | v223.52,80.26 224.54,80.26 E99.6 | v214.63,80.26 213.61,80.26 E86.6 | 202.69,84.84 204.22,84.84 E90.13 | 202.69,84.84 202.69,80.52 v202.44,80.26 | v194.31,78.99 193.29,78.99 E93.8 | v165.86,85.6 167.64,87.38 167.64,89.41 v170.18,91.95 | v201.17,90.68 202.69,89.15 202.69,84.84 | v241.55,79.25 242.57,79.25 U$15.S1
  Bottom 0.254: v194.31,78.99 195.33,80.01 202.18,80.01 v202.44,80.26 214.38,80.26 v214.63,80.26 v223.52,80.26 223.77,80.01 224.54,79.25 v241.55,79.25 | v165.1,81.03 164.08,82.04 164.08,85.6 v165.86,85.6 | v170.18,91.95 170.69,91.44 200.41,91.44 v201.17,90.68
S11  (via drill 0.61)
  Top 0.254: v176.53,19.05 175.51,19.05 E117.2 | E114.2 185.17,19.05 v184.15,19.05 183.9,18.8 183.9,12.95 182.88,11.94 v182.88,1.52 182.88,1.27 168.15,1.27 160.78,8.64 160.78,8.89 159.51,8.89 156.46,11.94 156.46,13.21 v155.7,13.97 | v171.45,16.76 170.43,16.76 E123.11 | v153.67,14.99 152.65,14.99 E126.5 | v233.68,18.8 232.66,18.8 E120.13 | v220.98,16.51 219.96,16.51 E107.11 218.19,16.51 217.42,15.75 217.42,4.57 v217.93,4.06 | v207.77,21.08 207.77,27.18 205.99,28.96 E110.8
  Bottom 0.254: v184.15,19.05 v176.53,19.05 176.28,18.8 173.48,18.8 v171.45,16.76 | v153.67,14.99 154.69,13.97 v155.7,13.97 | U$18.S2 242.57,14.48 238,14.48 v233.68,18.8 233.43,18.54 231.65,16.76 221.23,16.76 v220.98,16.51 220.73,16.76 216.66,20.83 208.03,20.83 v207.77,21.08 | v182.88,1.52 183.13,1.78 215.65,1.78 v217.93,4.06
S12  (via drill 0.61)
  Top 0.254: E126.12 159,17.53 160.53,17.53 160.53,17.27 161.04,16.76 161.04,16.51 162.31,15.24 E123.5 164.08,14.99 v165.1,14.99 | v223.52,14.22 224.54,14.22 E120.6 | v214.63,14.22 213.61,14.22 E107.6 | 202.69,18.8 204.22,18.8 E111.13 | 202.69,18.8 202.69,14.48 v202.44,14.22 | v194.31,12.95 193.29,12.95 E114.8 | v165.86,19.56 167.64,21.34 167.64,23.37 v170.18,25.91 | v201.17,24.64 202.69,23.11 202.69,18.8 | v241.55,13.21 242.57,13.21 U$18.S1
  Bottom 0.254: v194.31,12.95 195.33,13.97 202.18,13.97 v202.44,14.22 214.38,14.22 v214.63,14.22 v223.52,14.22 223.77,13.97 224.54,13.21 v241.55,13.21 | v165.1,14.99 164.08,16 164.08,19.56 v165.86,19.56 | v170.18,25.91 170.69,25.4 200.41,25.4 v201.17,24.64
T1  (via drill 0.61)
  Top 0.254: v59.69,110.74 58.67,110.74 E27.3 | E30.4 69.6,111.51 69.6,111.25 v68.58,111.25 68.33,111 67.06,109.73 v67.06,109.22 | E39.12 86.11,110.24 v85.09,110.24 82.8,110.24 E33.3 81.03,110.49 v80.01,110.49 | v97.79,106.68 99.31,106.68 101.35,108.71 101.35,112.78 99.31,112.78 E42.10 | v18.54,119.89 18.54,120.14 22.1,120.14 22.86,119.38 22.86,118.87 21.84,117.86 21.84,110.74 v22.86,110.74 23.88,110.74 E36.12 | v35.56,113.03 36.58,113.03 E23.10
  Bottom 0.254: v59.69,110.74 60.2,111.25 v68.58,111.25 68.83,111.25 79.25,111.25 v80.01,110.49 | v97.79,106.68 96.77,107.7 87.63,107.7 v85.09,110.24 | v18.54,119.89 17.27,118.62 13.97,118.62 U$6.T2 | v22.86,110.74 24.13,112.01 34.54,112.01 v35.56,113.03 35.81,112.78 36.58,112.78 36.58,111.76 39.37,108.97 39.62,108.97 40.64,107.95 45.97,107.95 46.23,108.2 62.48,108.2 63.5,109.22 v67.06,109.22
T2  (via drill 0.61)
  Top 0.254: v59.69,44.7 58.67,44.7 E9.3 | E12.4 69.6,45.47 69.6,45.21 v68.58,45.21 68.33,44.96 67.06,43.69 v67.06,43.18 | E18.12 86.11,44.2 v85.09,44.2 82.8,44.2 E15.3 81.03,44.45 v80.01,44.45 | v97.79,40.64 99.31,40.64 101.35,42.67 101.35,46.74 99.31,46.74 E21.10 | v18.54,53.85 18.54,54.1 22.1,54.1 22.86,53.34 22.86,52.83 21.84,51.82 21.84,44.7 v22.86,44.7 23.88,44.7 E3.12 | v35.56,46.99 36.58,46.99 E6.10
  Bottom 0.254: v59.69,44.7 60.2,45.21 v68.58,45.21 68.83,45.21 79.25,45.21 v80.01,44.45 | v97.79,40.64 96.77,41.66 87.63,41.66 v85.09,44.2 | v18.54,53.85 17.27,52.58 13.97,52.58 U$1.T2 | v22.86,44.7 24.13,45.97 34.54,45.97 v35.56,46.99 35.81,46.74 36.58,46.74 36.58,45.72 39.37,42.93 39.62,42.93 40.64,41.91 45.97,41.91 46.23,42.16 62.48,42.16 63.5,43.18 v67.06,43.18
T3  (via drill 0.61)
  Top 0.254: v59.69,176.78 58.67,176.78 E48.3 | E51.4 69.6,177.55 69.6,177.29 v68.58,177.29 68.33,177.04 67.06,175.77 v67.06,175.26 | E60.12 86.11,176.28 v85.09,176.28 82.8,176.28 E54.3 81.03,176.53 v80.01,176.53 | v97.79,172.72 99.31,172.72 101.35,174.75 101.35,178.82 99.31,178.82 E63.10 | v18.54,185.93 18.54,186.18 22.1,186.18 22.86,185.42 22.86,184.91 21.84,183.9 21.84,176.78 v22.86,176.78 23.88,176.78 E57.12 | v35.56,179.07 36.58,179.07 E44.10
  Bottom 0.254: v59.69,176.78 60.2,177.29 v68.58,177.29 68.83,177.29 79.25,177.29 v80.01,176.53 | v97.79,172.72 96.77,173.74 87.63,173.74 v85.09,176.28 | v18.54,185.93 17.27,184.66 13.97,184.66 U$9.T2 | v22.86,176.78 24.13,178.05 34.54,178.05 v35.56,179.07 35.81,178.82 36.58,178.82 36.58,177.8 39.37,175.01 39.62,175.01 40.64,173.99 45.97,173.99 46.23,174.24 62.48,174.24 63.5,175.26 v67.06,175.26
T4  (via drill 0.61)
